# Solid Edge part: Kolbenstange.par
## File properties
Username: ahadarics
Dokumentum tartalom típus: 0
Author: ahadarics
Last saved by: ahadarics
Revision: 85
Sűrűség: 0,000 kg/m^3
Pontosság: 0,990
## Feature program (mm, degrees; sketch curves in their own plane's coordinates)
base feature "unnamed BaseFeature 1"
sketch for "unnamed Protrusion 1" plane through (64, 0, 0) normal (1, 0, 0) x-axis (0, 1, 0)
  circle centre (0, 0) radius 12.5
extrude "unnamed Protrusion 1" add finite 33 along -normal
thread "Menet_2"  ThreadDepth = 22 mm
chamfer "Letörés_1" setback 0.7
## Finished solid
Body 1: solid body, 13 faces, 23 edges, 12 vertices.
  Faces by surface: plane 9, cylinder 3, cone 1
  Edges by curve: line 12, circle 11
Bounding box of the edges (mm): 300.500 x 25.000 x 25.000, from (-236.5, -12.5, -12.5) to (64, 12.5, 12.5).
Cylindrical faces by radius (mm): R5 x2, R12.5 x1
Conical faces (half-angle, radius in mm at the cone's reference point): 45 deg R4.3 x1
Planar faces by outward normal: +x 3, +z 1, -x 4, -z 1
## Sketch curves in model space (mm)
circle centre (64, 0, 0) radius 12.5
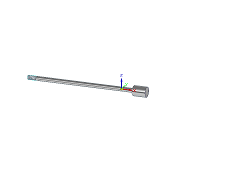
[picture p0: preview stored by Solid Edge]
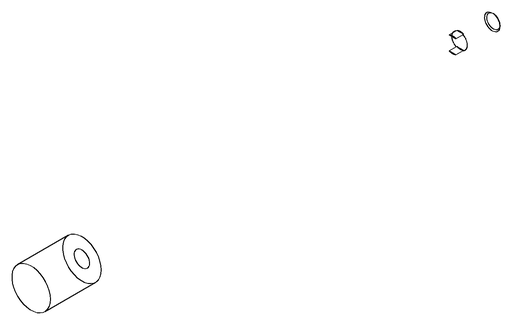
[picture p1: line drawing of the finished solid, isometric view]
